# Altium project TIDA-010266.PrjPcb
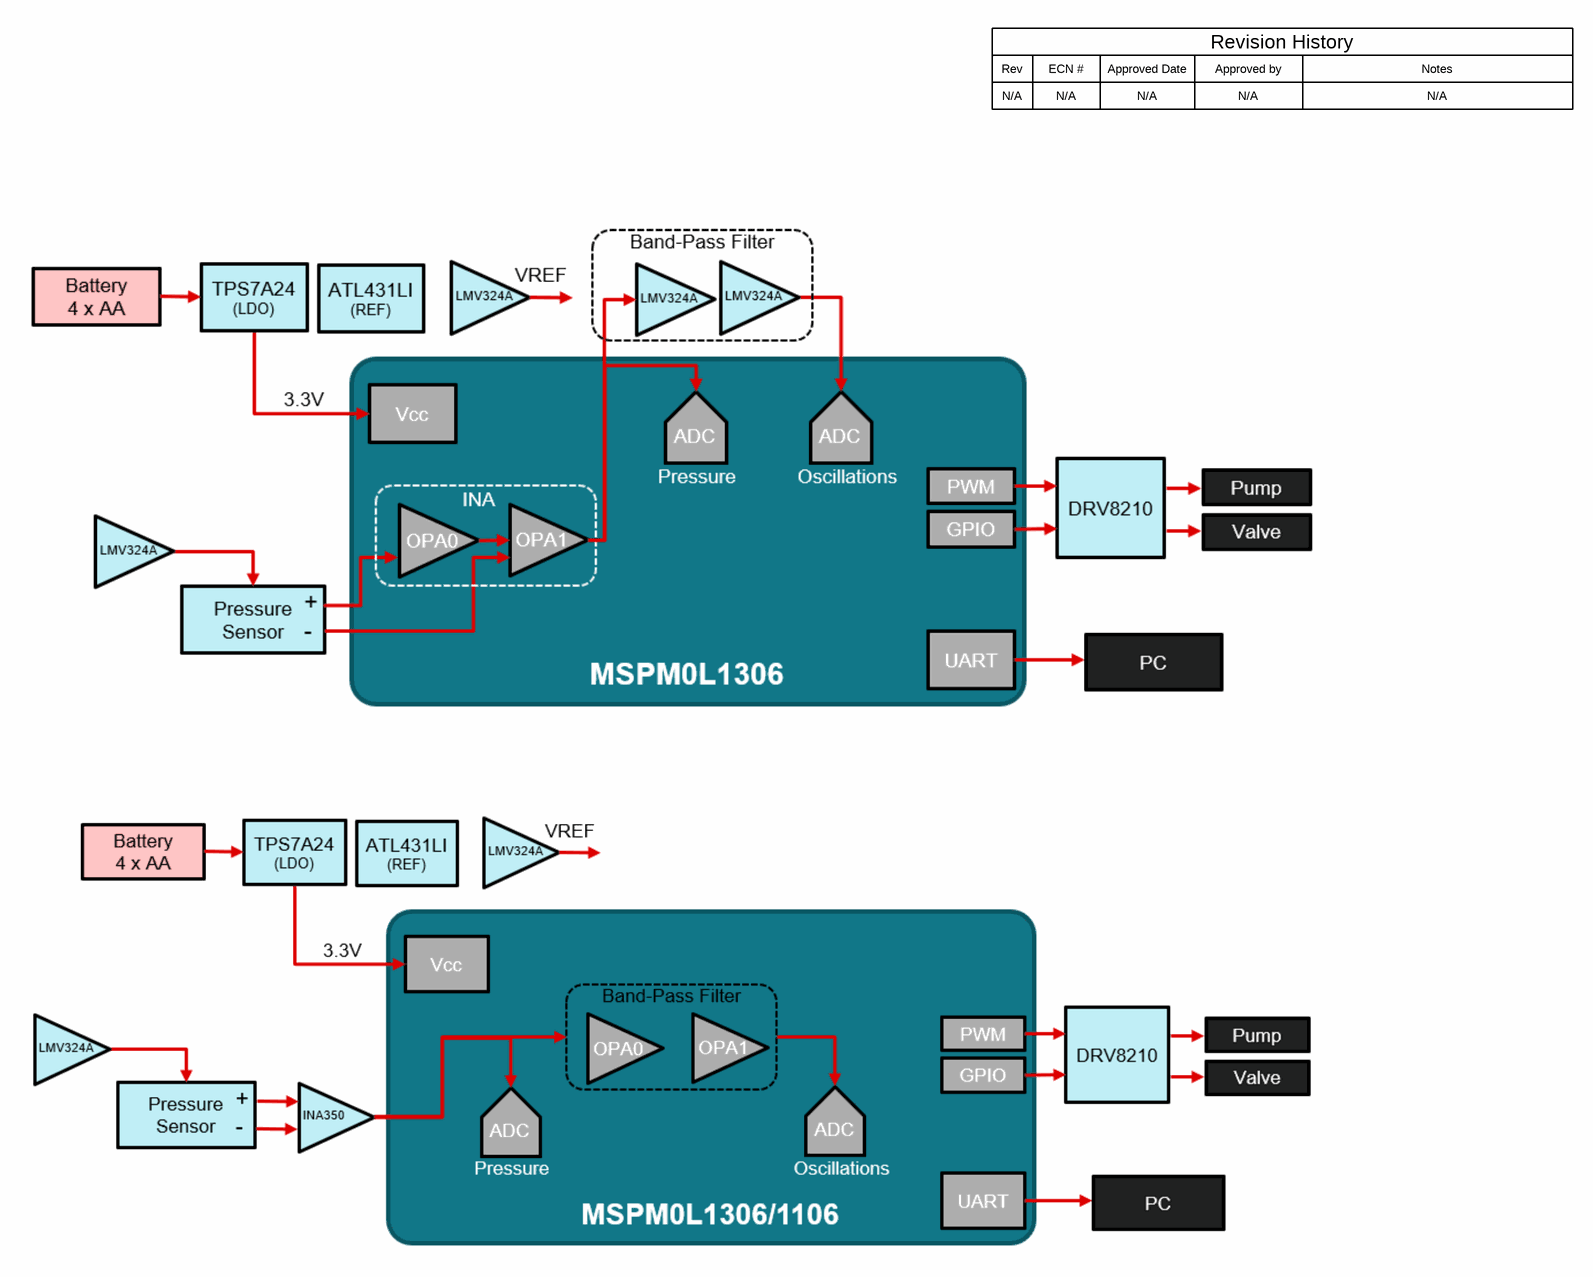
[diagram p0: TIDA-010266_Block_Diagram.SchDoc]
TID: 010266; TechSupport: http://www.ti.com/support; SCH_Rev: A; PRJ_Title: Low cost blood pressure and heart rate monitor; PRJ_Number: TIDA-010266; PRJ_Engineer: John Varela; PRJ_Customer: Public Release; PCB_Rev: A; PCB_Layout: John Varela; CopyrightYear: 2023
3 sheets, 89 parts. Net scope: global (net labels, ports and power ports of the same name join across sheets).
Board file: TIDA-010266.PcbDoc
Sheets:
  TIDA-010266_Block_Diagram.SchDoc
  TIDA-010266_BPM.SchDoc
  TIDA-010266_Hardware.SchDoc

## Sheet TIDA-010266_Block_Diagram.SchDoc
size 431 x 279 mm; Date: Not shown in title block; ApprovedBy: Not shown in title block; CheckedBy: Not shown in title block; Author: Not shown in title block; CompanyName: Not shown in title block; Engineer: Not shown in title block; Organization: Not shown in title block; Address1: Not shown in title block; Address2: Not shown in title block; Address3: Not shown in title block; Address4: Not shown in title block; DocumentNumber: 1; Revision: Use project parameter SCH_Rev; SheetNumber: 1; SheetTotal: 3; PageSetup: Record=PageOptions¦CenterHorizontal=True¦CenterVertical=True¦PrintScale=1.00¦XCorrection=1.00¦YCorrection=1.00¦PrintKind=0¦BorderSize=5000000¦LeftOffset=0¦BottomOffset=0¦Orientation=2¦PaperLength=1000¦PaperWidth=1000¦Scale=100¦PaperSource=15¦PrintQuality=600¦MediaType=1¦DitherType=10¦PaperKind=Letter¦PrintScaleMode=1

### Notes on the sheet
- Rev
- N/A
- ECN #
- Approved Date
- Approved by
- Revision History
- Notes

## Sheet TIDA-010266_BPM.SchDoc
size 431 x 279 mm; Date: Not shown in title block; ApprovedBy: Not shown in title block; CheckedBy: Not shown in title block; Author: Not shown in title block; CompanyName: Not shown in title block; Engineer: Not shown in title block; Organization: Not shown in title block; Address1: Not shown in title block; Address2: Not shown in title block; Address3: Not shown in title block; Address4: Not shown in title block; DocumentNumber: 2; Revision: Use project parameter SCH_Rev; SheetNumber: 2; SheetTotal: 3; PageSetup: Record=PageOptions¦CenterHorizontal=True¦CenterVertical=True¦PrintScale=1.00¦XCorrection=1.00¦YCorrection=1.00¦PrintKind=0¦BorderSize=5000000¦LeftOffset=0¦BottomOffset=0¦Orientation=2¦PaperLength=1000¦PaperWidth=1000¦Scale=100¦PaperSource=15¦PrintQuality=600¦MediaType=1¦DitherType=10¦PaperKind=Letter¦PrintScaleMode=1
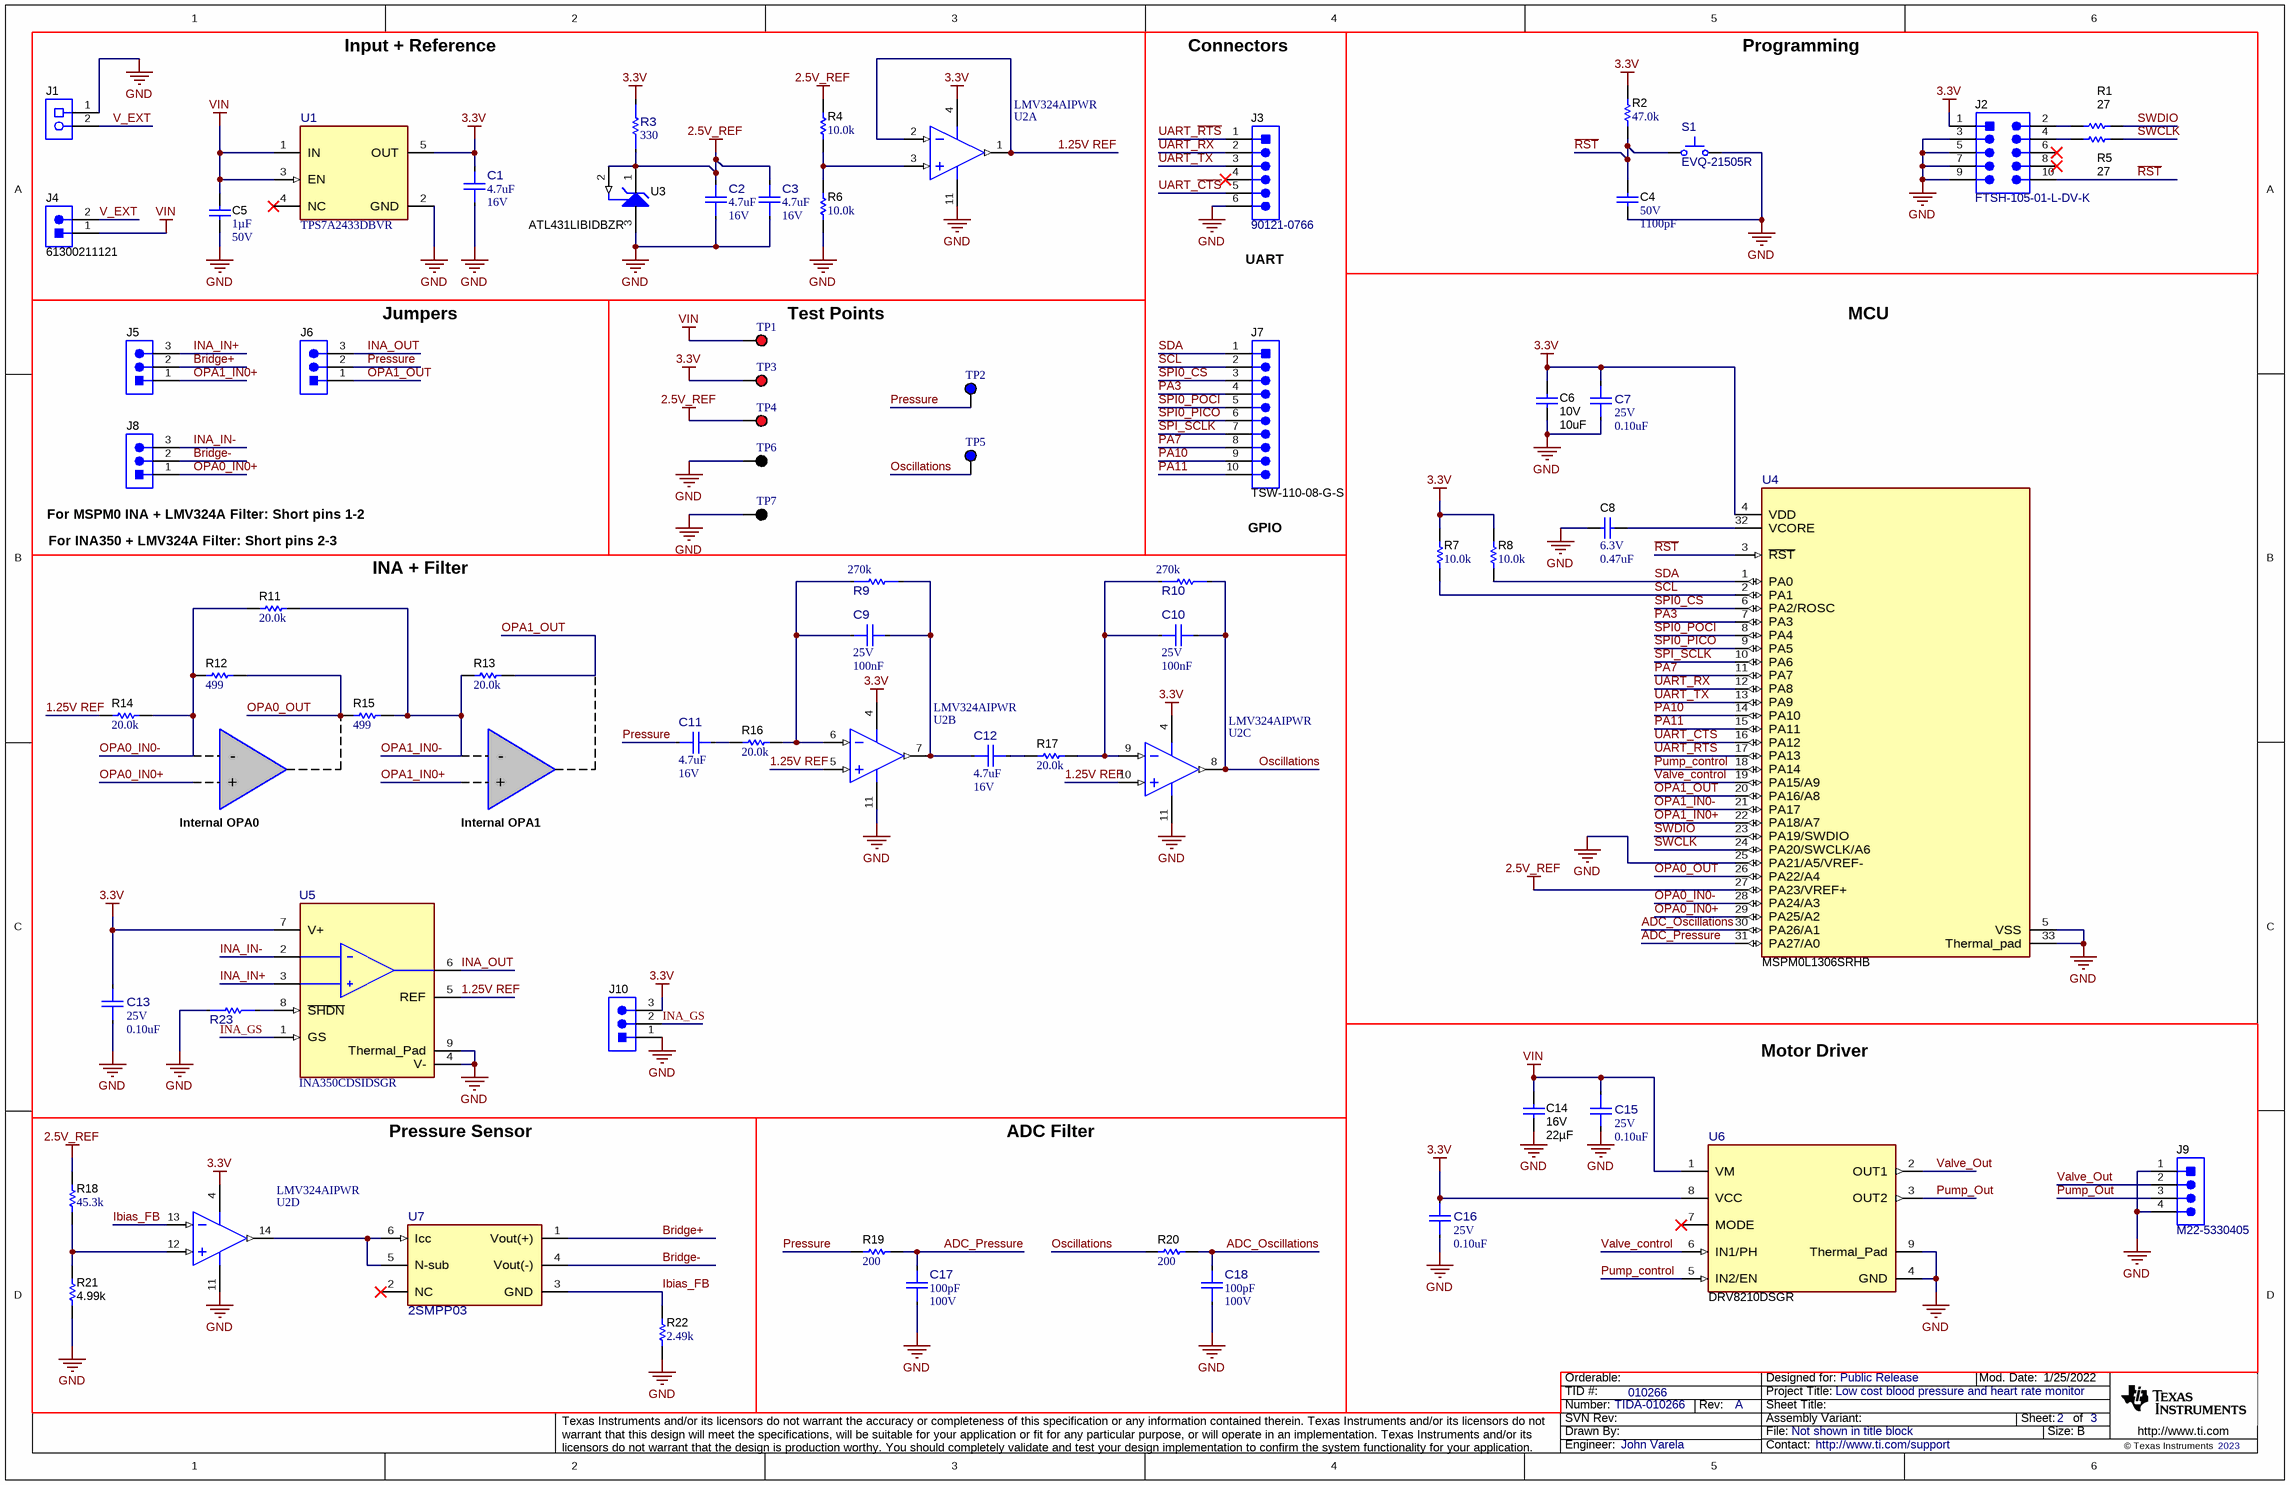
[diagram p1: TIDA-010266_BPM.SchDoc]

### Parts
C1  ValueDisplayed: 4.7uF  VDC_V: 16V  [FP-GRM188R61C475KE11D_0603-MFG]  (hidden comment: GRM188R61C475KE11D)
C2  ValueDisplayed: 4.7uF  VDC_V: 16V  [FP-GRM188R61C475KE11D_0603-MFG]  (hidden comment: GRM188R61C475KE11D)
C3  ValueDisplayed: 4.7uF  VDC_V: 16V  [FP-GRM188R61C475KE11D_0603-MFG]  (hidden comment: GRM188R61C475KE11D)
C4  VDC_V: 50V  ValueDisplayed: 1100pF  [0603]  (hidden comment: GRM1885C1H112JA01D)
C5  Cap_F: 1µF  VDC_V: 50V  [0805_HV]  (hidden comment: GCM21BR71H105KA03K)
C6  VDC_V: 10V  ValueDisplayed: 10uF  [0603]  (hidden comment: GRM188R61A106ME69D)
C7  ValueDisplayed: 0.10uF  VDC_V: 25V  [FP-GRM155R71E104KE14J_0402-MFG]  (hidden comment: GRM155R71E104KE14J)
C8  VDC_V: 6.3V  ValueDisplayed: 0.47uF  [0402]  (hidden comment: GRM155C80J474KE19D)
C9  VDC_V: 25V  Cap_F: 100nF  [FP-GCJ188R71E104KA12D_0603-MFG]  (hidden comment: GCJ188R71E104KA12D)
C10  VDC_V: 25V  Cap_F: 100nF  [FP-GCJ188R71E104KA12D_0603-MFG]  (hidden comment: GCJ188R71E104KA12D)
C11  ValueDisplayed: 4.7uF  VDC_V: 16V  [FP-GRM188R61C475KE11D_0603-MFG]  (hidden comment: GRM188R61C475KE11D)
C12  ValueDisplayed: 4.7uF  VDC_V: 16V  [FP-GRM188R61C475KE11D_0603-MFG]  (hidden comment: GRM188R61C475KE11D)
C13  ValueDisplayed: 0.10uF  VDC_V: 25V  [FP-GRM155R71E104KE14J_0402-MFG]  (hidden comment: GRM155R71E104KE14J)
C14  VDC_V: 16V  ValueDisplayed: 22µF  [0603]  (hidden comment: CL10A226MO7JZNC)
C15  ValueDisplayed: 0.10uF  VDC_V: 25V  [FP-GRM155R71E104KE14J_0402-MFG]  (hidden comment: GRM155R71E104KE14J)
C16  ValueDisplayed: 0.10uF  VDC_V: 25V  [FP-GRM155R71E104KE14J_0402-MFG]  (hidden comment: GRM155R71E104KE14J)
C17  ValueDisplayed: 100pF  VDC_V: 100V  [FP-GCM1885C2A101JA16J_0603-MFG]  (hidden comment: GCM1885C2A101JA16J)
C18  ValueDisplayed: 100pF  VDC_V: 100V  [FP-GCM1885C2A101JA16J_0603-MFG]  (hidden comment: GCM1885C2A101JA16J)
J1  CMP-0054828-1  [Wurth_691101710002]  (value not drawn)
J2  FTSH-105-01-L-DV-K  [Samtec_FTSH-105-01-x-DV-K]
J3  90121-0766  [Molex_90121-0766]
J4  61300211121  [WURTH_61300211121]
J5  61300311121  [WURTH_61300311121]  (value not drawn)
J6  61300311121  [WURTH_61300311121]  (value not drawn)
J7  TSW-110-08-G-S  [Samtec_TSW-110-08-x-S]
J8  61300311121  [WURTH_61300311121]  (value not drawn)
J9  M22-5330405  [Harwin_M22-5330405]
J10  61300311121  [WURTH_61300311121]  (value not drawn)
R1  ValueDisplayed: 27  [0603]  (hidden comment: CRCW060327R0JNEA)
R2  ValueDisplayed: 47.0k  [0603]  (hidden comment: CRCW060347K0FKEA)
R3  value 330  [FP-CRCW0603330RFKEA_0603-MFG]  (hidden comment: CRCW0603330RFKEA)
R4  ValueDisplayed: 10.0k  [0603]  (hidden comment: CRCW060310K0FKEA)
R5  ValueDisplayed: 27  [0603]  (hidden comment: CRCW060327R0JNEA)
R6  ValueDisplayed: 10.0k  [0603]  (hidden comment: CRCW060310K0FKEA)
R7  ValueDisplayed: 10.0k  [0603]  (hidden comment: CRCW060310K0FKEA)
R8  ValueDisplayed: 10.0k  [0603]  (hidden comment: CRCW060310K0FKEA)
R9  value 270k  [FP-CRCW0603270KFKEA_0603-MFG]  (hidden comment: CRCW0603270KFKEA)
R10  value 270k  [FP-CRCW0603270KFKEA_0603-MFG]  (hidden comment: CRCW0603270KFKEA)
R11  ValueDisplayed: 20.0k  [0603]  (hidden comment: CRCW060320K0FKEA)
R12  ValueDisplayed: 499  [0603]  (hidden comment: CRCW0603499RFKEAC)
R13  ValueDisplayed: 20.0k  [0603]  (hidden comment: CRCW060320K0FKEA)
R14  ValueDisplayed: 20.0k  [0603]  (hidden comment: CRCW060320K0FKEA)
R15  ValueDisplayed: 499  [0603]  (hidden comment: CRCW0603499RFKEAC)
R16  ValueDisplayed: 20.0k  [0603]  (hidden comment: CRCW060320K0FKEA)
R17  ValueDisplayed: 20.0k  [0603]  (hidden comment: CRCW060320K0FKEA)
R18  ValueDisplayed: 45.3k  [0603]  (hidden comment: CRCW060345K3FKEA)
R19  ValueDisplayed: 200  [0603]  (hidden comment: CRCW0603200RFKEA)
R20  ValueDisplayed: 200  [0603]  (hidden comment: CRCW0603200RFKEA)
R21  ValueDisplayed: 4.99k  [0603]  (hidden comment: CRCW06034K99FKEAC)
R22  ValueDisplayed: 2.49k  [0603]  (hidden comment: RT0603BRD072K49L)
R23  RC0402FR-070RL  [FP-RC0402FR-070RL_0402-MFG]  (value not drawn)
S1  EVQ-21505R  [SW_EVQ-21x05]
TP1  5000  [Keystone5000]  (value not drawn)
TP2  5117  [Keystone5117]  (value not drawn)
TP3  5000  [Keystone5000]  (value not drawn)
TP4  5000  [Keystone5000]  (value not drawn)
TP5  5117  [Keystone5117]  (value not drawn)
TP6  5001  [Keystone5001]  (value not drawn)
TP7  5001  [Keystone5001]  (value not drawn)
U1  TPS7A2433DBVR  [DBV0005A-MFG]
U2  LMV324AIPWR  [PW0014A-MFG]  (parts A,B,C,D of 4)
U3  ATL431LIBIDBZR  [DBZ0003A_N]
U4  MSPM0L1306SRHB  [RHB0032N-MFG]
U5  INA350CDSIDSGR  [DSG0008A-MFG]
U6  DRV8210DSGR  [DSG0008A-MFG]
U7  2SMPP03  [FP-2SMPP03_SMD6-MFG]

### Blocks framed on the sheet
Input + Reference: C1-C3 C5 J1 J4 R3 R4 R6 U1-U3
Connectors: J3 J7
Programming: C4 J2 R1 R2 R5 S1
INA + Filter: C9-C13 J10 R9-R17 R23 U2 U5
Motor Driver: C14-C16 J9 U6
Pressure Sensor: R18 R21 R22 U2 U7
ADC Filter: C17 C18 R19 R20

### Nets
2.5V_REF: C2.2 C3.2 R3.1 R4.2 R18.2 TP4.1 U3.1(CATHODE) U3.2(REF) U4.27(PA23/VREF+)
3.3V: C1.2 C6.1 C7.2 C13.2 C16.2 J2.1 J10.3 R2.2 R3.2 R7.2 R8.2 TP3.1 U1.5(OUT) U2.4(V+) U4.4(VDD) U5.7(V+) U6.8(VCC)
GND: C1.1 C2.1 C3.1 C4.2 C5.2 C6.2 C7.1 C8.2 C13.1 C14.2 C15.2 C16.1 C17.1 C18.1 J1.1 J2.3 J2.5 J2.7 J2.9 J3.6 J9.1 J9.4 J10.1 R6.1 R21.1 R22.1 R23.1 S1.2 TP6.1 TP7.1 U1.2(GND) U2.11(V-) U3.3(ANODE) U4.5(VSS) U4.25(PA21/A5/VREF-) U4.33(Thermal_pad) U5.4(V-) U5.9(Thermal_Pad) U6.4(GND) U6.9(Thermal_Pad)
VIN: C5.1 C14.1 C15.1 J4.1 TP1.1 U1.1(IN) U1.3(EN) U6.1(VM)
1.25V REF: R14.1 U2.1(OUTA) U2.2(INA-) U2.5(INB+) U2.10(INC+) U5.5(REF)
~{RST}: C4.1 J2.10 R2.1 S1.1 U4.3(~{RST})
ADC_Oscillations: C18.2 R20.2 U4.30(PA26/A1)
ADC_Pressure: C17.2 R19.2 U4.31(PA27/A0)
Bridge+: J5.2 U7.1(Vout(+))
Bridge-: J8.2 U7.4(Vout(-))
Ibias_FB: R22.2 U2.13(IND-) U7.3(GND)
INA_GS: J10.2 U5.1(GS)
INA_IN+: J5.3 U5.3(IN+)
INA_IN-: J8.3 U5.2(IN-)
INA_OUT: J6.3 U5.6(OUT)
OPA0_IN0+: J8.1 U4.29(PA25/A2)
OPA0_IN0-: R11.1 R12.1 R14.2 U4.28(PA24/A3)
OPA0_OUT: R12.2 R15.1 U4.26(PA22/A4)
OPA1_IN0+: J5.1 U4.22(PA18/A7)
OPA1_IN0-: R11.2 R13.1 R15.2 U4.21(PA17)
OPA1_OUT: J6.1 R13.2 U4.20(PA16/A8)
Oscillations: C10.2 R10.2 R20.1 TP5.1 U2.8(OUTC)
PA3: J7.4 U4.7(PA3)
PA7: J7.8 U4.11(PA7)
PA10: J7.9 U4.14(PA10)
PA11: J7.10 U4.15(PA11)
Pressure: C11.1 J6.2 R19.1 TP2.1
Pump_control: U4.18(PA14) U6.5(IN2/EN)
Pump_Out: J9.3 U6.3(OUT2)
SCL: J7.2 R7.1 U4.2(PA1)
SDA: J7.1 R8.1 U4.1(PA0)
SPI0_CS: J7.3 U4.6(PA2/ROSC)
SPI0_PICO: J7.6 U4.9(PA5)
SPI0_POCI: J7.5 U4.8(PA4)
SPI_SCLK: J7.7 U4.10(PA6)
SWCLK: R5.2 U4.24(PA20/SWCLK/A6)
SWDIO: R1.2 U4.23(PA19/SWDIO)
UART_~{CTS}: J3.5 U4.16(PA12)
UART_~{RTS}: J3.1 U4.17(PA13)
UART_RX: J3.2 U4.12(PA8)
UART_TX: J3.3 U4.13(PA9)
V_EXT: J1.2 J4.2
Valve_control: U4.19(PA15/A9) U6.6(IN1/PH)
Valve_Out: J9.2 U6.2(OUT1)
NetC8_1: C8.1 U4.32(VCORE)
NetC9_1: C9.1 R9.1 R16.2 U2.6(INB-)
NetC9_2: C9.2 C12.1 R9.2 U2.7(OUTB)
NetC10_1: C10.1 R10.1 R17.2 U2.9(INC-)
NetC11_2: C11.2 R16.1
NetC12_2: C12.2 R17.1
NetJ2_2: J2.2 R1.1
NetJ2_4: J2.4 R5.1
NetR4_1: R4.1 R6.2 U2.3(INA+)
NetR18_1: R18.1 R21.2 U2.12(IND+)
NetR23_2: R23.2 U5.8(~{SHDN})
NetU2_14: U2.14(OUTD) U7.5(N-sub) U7.6(Icc)

Not connected (* = marked no-connect by the designer): J2 6* 8*; J3 4*; U1 4(NC)*; U6 7(MODE)*; U7 2(NC)*

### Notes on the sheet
- (near J3) UART
- Jumpers
- (near TP1) Test Points
- MCU
- For INA350 + LMV324A Filter: Short pins 2-3
- (near J8) For MSPM0 INA + LMV324A Filter: Short pins 1-2
- GPIO
- -
- Internal OPA0
- +
- Internal OPA1

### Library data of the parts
C1-C3 C11 C12 = CMP-0098153-1: Chip Multilayer Ceramic Capacitors for General Purpose, 0603, 4.7uF, X5R, 15%, 10%, 16V; Manufacturer: Murata; SizeZ_mm: 0.95mm; Cap_F: 4.7µF; Value: 4.7µF; AEC Qualified: No
C4 = CMP-0007177-4: CAP, CERM, 1100 pF, 50 V, +/- 5%, C0G/NP0, 0603; Manufacturer: MuRata; TaMin_C: -55°C; Polarized: N; SizeAreaWB_mm2: 4.68; Value1: Unknown; U/M: EA; Value: 1100pF; TaMax_C: 125°C; SizeZ_mm: 1; SizeX_mm: 1.6; SizeY_mm: 0.8; SizeArea_mm2: 1.28; Cap_F: 1.1nF; AEC Category: Q200
C5 = CMP-0086249-1: CAP, CERM, 1 µF, 50 V,+/- 10%, X7R, AEC-Q200 Grade 1, 0805; Manufacturer: MuRata; Value: 1uF; AEC Qualified: Y; AEC Category: Q200; U/M: EA; AEC Grade: 1; SizeArea_mm2: 2.5; SizeAreaWB_mm2: 6.75; SizeZ_mm: 1.45; SizeX_mm: 2; Cap_Case: 0805; TaMax_C: 125°C; Polarized: N; SizeY_mm: 1.25; TaMin_C: -55°C
C6 = CMP-0007318-3: CAP, CERM, 10 uF, 10 V, +/- 20%, X5R, 0603; Manufacturer: MuRata; TaMin_C: -55°C; Polarized: N; SizeAreaWB_mm2: 4.68; Value1: Unknown; U/M: EA; Value: 10uF; TaMax_C: 85°C; SizeZ_mm: 1; SizeX_mm: 1.6; SizeY_mm: 0.8; SizeArea_mm2: 1.28; Cap_F: 10µF; AEC Category: Q200
C7 C13 C15 C16 = CMP-0095279-1: Chip Multilayer Ceramic Capacitors for General Purpose, 0402, 0.10uF, X7R, 15%, 10%, 25V; Manufacturer: Murata; Value: 100nF; SizeZ_mm: 0.55mm; AEC Qualified: No
C8 = CMP-0006525-2: CAP, CERM, 0.47 uF, 6.3 V, +/- 10%, X6S, 0402; Manufacturer: MuRata; TaMin_C: -55°C; Polarized: N; SizeAreaWB_mm2: 3; Value1: Unknown; U/M: EA; Value: 0.47uF; TaMax_C: 105°C; SizeZ_mm: 0.6; SizeX_mm: 1; SizeY_mm: 0.5; Cap_F: 470nF; AEC Category: Q200
C9 C10 = CMP-0095670-2: Cap Ceramic 0.1uF 25V X7R 10% Pad SMD 0603 Soft Termination +125°C Automotive T/R; Manufacturer: Murata; Value: 100nF; AEC Qualified: Yes; AEC Grade: Grade 1; SizeZ_mm: 0.9mm; TempCo: 15%
C14 = CMP-0081159-1: CAP, CERM, 22 µF, 16 V,+/- 20%, X5R, 0603; Manufacturer: Samsung; SizeAreaWB_mm2: 4.68; SizeArea_mm2: 1.28; AEC Qualified: N; AEC Category: Q200; Value: 22uF; TaMax_C: 85°C; SizeZ_mm: 1; TaMin_C: -55°C; SizeY_mm: 0.8; U/M: EA; SizeX_mm: 1.6
C17 C18 = CMP-0120248-1: Ceramic Capacitor for Automotive 100pF  ±5% 100VDC C0G 0603 Paper T/R; Manufacturer: Murata; AEC Grade: Grade 1; AEC Qualified: Yes; SizeZ_mm: 0.9mm; TempCo: 30ppm/°C
J1 = CMP-0054828-1: Terminal Block, 5 mm, 2x1, Tin, TH; PartNumber: 691 101 710 002; Manufacturer: Wurth Elektronik; CNHeader: FALSE; Green_Lifecycle: Active; Green_REACh: Passed; CT: TRUE
J2 = CMP-0075634-2: Header(Shrouded), 1.27mm, 5x2, Gold, SMT; Manufacturer: Samtec; Pitch_mm: 1.27; Gender: Male; Cert_CSA: Y; Current_A: 3.3A; Row_Count: 2
J3 = CMP-0055334-1: Header, 2.54mm, 6x1, Gold, R/A, TH; Manufacturer: Molex; CNHeader: TRUE; Current_A: 3A; Shrouded: N; Gender: Male; Voltage_V: 350V; Row_Count: 1; Pitch_mm: 2.54; CT: FALSE; Cert_UL: Y
J4 = CMP-0054794-2: Header, 2.54 mm, 2x1, Gold, TH; Manufacturer: Wurth Elektronik; Shrouded: N; Gender: Male; Green_REACh: Passed; Pitch_mm: 2.54; Green_Lifecycle: Active; Row_Count: 1; Cert_UL: Y
J5 J6 J8 J10 = CMP-0054796-1: Header, 2.54 mm, 3x1, Gold, TH; Manufacturer: Wurth Elektronik; Green_Lifecycle: Active; Green_REACh: Passed; CNHeader: TRUE; CT: FALSE
J7 = CMP-0055600-1: Header, 2.54mm, 10x1, Gold, TH; Manufacturer: Samtec; CNHeader: TRUE; Current_A: 6.3A; Shrouded: N; Gender: Male; Cert_CSA: Y; Voltage_V: 550V; Row_Count: 1; Pitch_mm: 2.54; CT: FALSE
J9 = CMP-0075150-1: Header, 2mm, 4x1, Gold, Black, R/A, SMT; Manufacturer: Harwin; CNHeader: True; Gender: Male; Row_Count: 1; Pitch_mm: 2; CT: False
R1 R5 = CMP-0025767-3: RES, 27, 5%, 0.1 W, 0603; Manufacturer: Vishay-Dale; Power_W: 100mW; TempCo: 200 ppm/C; Value_Code: 27R0; U/M: EA; Value: 27; EIA_Code: E24; SizeX_mm: 1.6; SizeY_mm: 0.8; SizeZ_mm: 1; Value2: 0.1W; SizeArea_mm2: 1.28; VDC_V: 75V; AEC Category: Q200
R2 = CMP-0022438-4: RES, 47.0 k, 1%, 0.1 W, AEC-Q200 Grade 0, 0603; Manufacturer: Vishay-Dale; Power_W: 100mW; TempCo: 100 ppm/C; Value_Code: 47k0; Value: 47.0k; Res_ohm: 47k; SizeX_mm: 1.6; SizeY_mm: 0.8; SizeZ_mm: 1; Value2: 0.1W; SizeArea_mm2: 1.28; AEC Qualified: Y; VDC_V: 75V; AEC Grade: 0; AEC Category: Q200
R3 = CMP-0120247-1: RES Thick Film, 330Ω, 1%, 0.1W, 100ppm/°C, 0603; Manufacturer: Vishay; Approved Alternate Part Number: 541-1.00HHCT-ND; AEC Grade: Grade 0; AEC Qualified: Yes; Power_W: 100mW; SizeZ_mm: 0.5mm; VDC_V: 75V
R4 R6-R8 = CMP-0021998-4: RES, 10.0 k, 1%, 0.1 W, AEC-Q200 Grade 0, 0603; Manufacturer: Vishay-Dale; Power_W: 100mW; TempCo: 100 ppm/C; Value_Code: 10k0; Value: 10.0k; EIA_Code: E96; Res_ohm: 10k; SizeX_mm: 1.6; SizeY_mm: 0.8; SizeZ_mm: 1; Value2: 0.1W; SizeArea_mm2: 1.28; AEC Qualified: Y; VDC_V: 75V; AEC Category: Q200; AEC Grade: 0
R9 R10 = CMP-0120246-1: RES Thick Film, 270kΩ, 1%, 0.1W, 100ppm/°C, 0603; Manufacturer: Vishay; Approved Alternate Part Number: 541-1.00HHCT-ND; AEC Grade: Grade 0; AEC Qualified: Yes; Power_W: 100mW; SizeZ_mm: 0.5mm; VDC_V: 75V
R11 R13 R14 R16 R17 = CMP-0022204-4: RES, 20.0 k, 1%, 0.1 W, AEC-Q200 Grade 0, 0603; Manufacturer: Vishay-Dale; Power_W: 100mW; TempCo: 100 ppm/C; Value_Code: 20k0; Value: 20.0k; EIA_Code: E96; Res_ohm: 20k; SizeX_mm: 1.6; SizeY_mm: 0.8; SizeZ_mm: 1; Value2: 0.1W; SizeArea_mm2: 1.28; AEC Qualified: Y; VDC_V: 75V; AEC Category: Q200; AEC Grade: 0
R12 R15 = CMP-0082532-1: RES, 499, 1%, 0.1 W, 0603; Manufacturer: Vishay-Dale; Power_W: 100mW; TempCo: 100 ppm/C; SizeAreaWB_mm2: 4.68; Value_Code: 499R; Value: 499; EIA_Code: E96; SizeX_mm: 1.6; SizeY_mm: 0.8; SizeZ_mm: 1; Value2: 0.1W; SizeArea_mm2: 1.28; AEC Qualified: N; VDC_V: 75V; AEC Category: Q200
R18 = CMP-0022430-4: RES, 45.3 k, 1%, 0.1 W, AEC-Q200 Grade 0, 0603; Manufacturer: Vishay-Dale; Power_W: 100mW; TempCo: 100 ppm/C; Value_Code: 45k3; Value: 45.3k; EIA_Code: E96; SizeX_mm: 1.6; SizeY_mm: 0.8; SizeZ_mm: 1; Value2: 0.1W; SizeArea_mm2: 1.28; AEC Qualified: Y; VDC_V: 75V; AEC Category: Q200; AEC Grade: 0
R19 R20 = CMP-0022201-5: RES, 200, 1%, 0.1 W, AEC-Q200 Grade 0, 0603; Manufacturer: Vishay-Dale; Power_W: 100mW; TempCo: 100 ppm/C; Value_Code: 200R; Value: 200; EIA_Code: E96; SizeX_mm: 1.6; SizeY_mm: 0.8; SizeZ_mm: 1; Value2: 0.1W; SizeArea_mm2: 1.28; AEC Qualified: Y; VDC_V: 75V; AEC Category: Q200; AEC Grade: 0
R21 = CMP-0082533-1: RES, 4.99 k, 1%, 0.1 W, 0603; Manufacturer: Vishay-Dale; Power_W: 100mW; TempCo: 100 ppm/C; SizeAreaWB_mm2: 4.68; Value_Code: 4k99; Value: 4.99k; EIA_Code: E96; SizeX_mm: 1.6; SizeY_mm: 0.8; SizeZ_mm: 1; Value2: 0.1W; SizeArea_mm2: 1.28; AEC Qualified: N; VDC_V: 75V; AEC Category: Q200
R22 = CMP-0024072-3: RES, 2.49 k, 0.1%, 0.1 W, 0603; Manufacturer: Yageo America; Power_W: 100mW; TempCo: 25 ppm/C; Value_Code: 2k49; U/M: EA; Value: 2.49k; EIA_Code: E192; SizeX_mm: 1.6; SizeY_mm: 0.8; SizeZ_mm: 1; Value2: 0.1W; SizeArea_mm2: 1.28; VDC_V: 75V; AEC Category: Q200
R23 = CMP-0095689-1: Jumper 0.063W, 1/16W Chip Resistor 0402 (1005 Metric) Moisture Resistant Thick Film; Manufacturer: Yageo; AEC Qualified: No; Value: 0; Power_W: 63mW; SizeZ_mm: 0.4mm
S1 = CMP-0002172-2: Switch, Tactile, SPST-NO, 0.02A, 15V, TH; Manufacturer: Panasonic; CurrentRating_mA: 20A; PositionCount: 1; SwitchFunction: Off-Mom
TP1 TP3 TP4 = CMP-0055137-1: Test Point, Miniature, Red, TH; Manufacturer: Keystone; CNHeader: FALSE; Green_Lifecycle: Active; Green_REACh: Passed; ContactFinish: Silver; CT: TRUE
TP2 TP5 = CMP-0055154-1: Test Point, Miniature, Blue, TH; Manufacturer: Keystone; CNHeader: FALSE; Green_Lifecycle: Active; Green_REACh: Passed; ContactFinish: Silver; CT: TRUE
TP6 TP7 = CMP-0055138-1: Test Point, Miniature, Black, TH; Manufacturer: Keystone; CNHeader: FALSE; Green_Lifecycle: Active; Green_REACh: Passed; ContactFinish: Silver; CT: TRUE
U1 = CMP-0120272-1: 200-mA, 18-V, ultra-low-IQ, low-dropout (LDO) voltage regulator with enable 5-SOT-23 -40 to 125; Manufacturer: Texas Instruments; SizeZ_mm: 1.45mm; AEC Qualified: No; Accuracy Percentage: 1.25%; Dropout Voltage: 160mV; Max Supply Voltage: 18V; Min Supply Voltage: 3.8V; Nominal Supply Current: 2-15uA; Number Of Outputs: 1; Output Type: Fixed; Output Voltage: 3.3V; Standoff Height: 0mm; TJmax_C: +125°C
U2 = CMP-0120268-2: Quad, 5.5-V, 1-MHz, 4-mV offset voltage, RRO operational amplifier 14-TSSOP -40 to 125; Manufacturer: Texas Instruments; SizeZ_mm: 1.2mm; AEC Qualified: No; Gain Bandwidth: 1MHz; Input Bias Current: 0.00001uA; Input Offset Voltage: 1mV; Max Dual Supply Voltage: 2.75V; Max Supply Voltage: 5.5V; Min Dual Supply Voltage: 1.25V; Min Supply Voltage: 2.5V; Nominal Supply Current: 70uA; Number Of Channels: 4; Output Current Per Channel: 40mA; Response Time: 4us; Standoff Height: 0.05mm; TaMax_C: +125°C; TaMin_C: -40°C; TJmax_C: +150°C; Voltage Gain: 98dB; AEC Category: Q200; CompType: IC
U3 = CMP-0084732-1: High Bandwidth Low-Iq Programmable Shunt Regulator, DBZ0003A (SOT-23-3); Manufacturer: Texas Instruments; SizeArea_mm2: 7.5; SizeY_mm: 3; SizeX_mm: 2.5; SizeAreaWB_mm2: 14; AEC Category: Q200; SizeZ_mm: 1.12; AEC Qualified: N; CompType: IC
U4 = CMP-0093968-1: MSPM0L130x Mixed-Signal Microcontrollers; Manufacturer: Texas Instruments; Number Of Pwm Channels: 8; TJmax_C: +130°C; Interface: I2C,SPI,UART,LIN,IrDA,SMBus; Number Of I2C Channels: 2; Memory Size: 64KBytes; Core Architecture: ARM Cortex-M0+; Number Of Spi Channels: 1; Min Supply Voltage: 1.62V; Ram Size: 4KBytes; Data Bus Width: 32bits; TaMax_C: +125°C; Frequency_Fixed: 32MHz; Memory Type: FLASH; Number Of Adc Channels: 10; Standoff Height: 0mm; AEC Qualified: No; Number Of I/Os: 28; TaMin_C: -40°C; SizeZ_mm: 1mm; Max Supply Voltage: 3.6V; Number Of Timers/Counters: 4
U5 = CMP-0120266-1: Cost and Size Optimized, Low Power, 1.8-V to 5.5-V Selectable Gain Instrumentation Amplifier; Manufacturer: Texas Instruments; SizeZ_mm: 0.8mm; AEC Qualified: No; Bandwidth: 100kHz; Input Bias Current: 0.00000065uA; Input Offset Voltage: 0.2mV; Max Dual Supply Voltage: 2.75V; Max Supply Voltage: 5.5V; Min Dual Supply Voltage: 900mV; Min Supply Voltage: 1.8V; Nominal Supply Current: 100uA; Number Of Channels: 1; Output Current Per Channel: 20mA; Response Time: 85us; Standoff Height: 0mm; TJmax_C: +150°C; Voltage Gain: 0.001V/mV
U6 = CMP-0090268-2: 11V, 1A H-bridge motor driver, PWM, PH/EN, ½ bridge control, with low power sleep mode; Manufacturer: Texas Instruments; Motor Type: Brushed; AEC Category: Q200; SizeZ_mm: 0.8mm; AEC Qualified: No; Min Supply Voltage: 1.65V; TJmax_C: +150°C; Switching Frequency: 100kHz; TaMax_C: +125°C; Number Of Outputs: 2; Standoff Height: 0mm; TaMin_C: -40°C; CompType: IC
U7 = CMP-0120245-1: Pressure Sensor ±7.25PSI (±50kPa) Compound Male - 0.1" (2.59mm) Tube -43 mV ~ 42 mV 6-SMD Module; Manufacturer: Omron Electronics Inc-EMC Div; AEC Qualified: No; Operating Supply Current: 100uA; Port Style: Barbless; Sensor Output: Analog Voltage; TaMax_C: +100°C; TaMin_C: -10°C

## Sheet TIDA-010266_Hardware.SchDoc
size 431 x 279 mm; Date: Not shown in title block; ApprovedBy: Not shown in title block; CheckedBy: Not shown in title block; Author: Not shown in title block; CompanyName: Not shown in title block; Engineer: Not shown in title block; Organization: Not shown in title block; Address1: Not shown in title block; Address2: Not shown in title block; Address3: Not shown in title block; Address4: Not shown in title block; DocumentNumber: 3; Revision: Use project parameter SCH_Rev; SheetNumber: 3; SheetTotal: 3; PageSetup: Record=PageOptions¦CenterHorizontal=True¦CenterVertical=True¦PrintScale=1.00¦XCorrection=1.00¦YCorrection=1.00¦PrintKind=0¦BorderSize=5000000¦LeftOffset=0¦BottomOffset=0¦Orientation=2¦PaperLength=1000¦PaperWidth=1000¦Scale=100¦PaperSource=15¦PrintQuality=600¦MediaType=1¦DitherType=10¦PaperKind=Letter¦PrintScaleMode=1
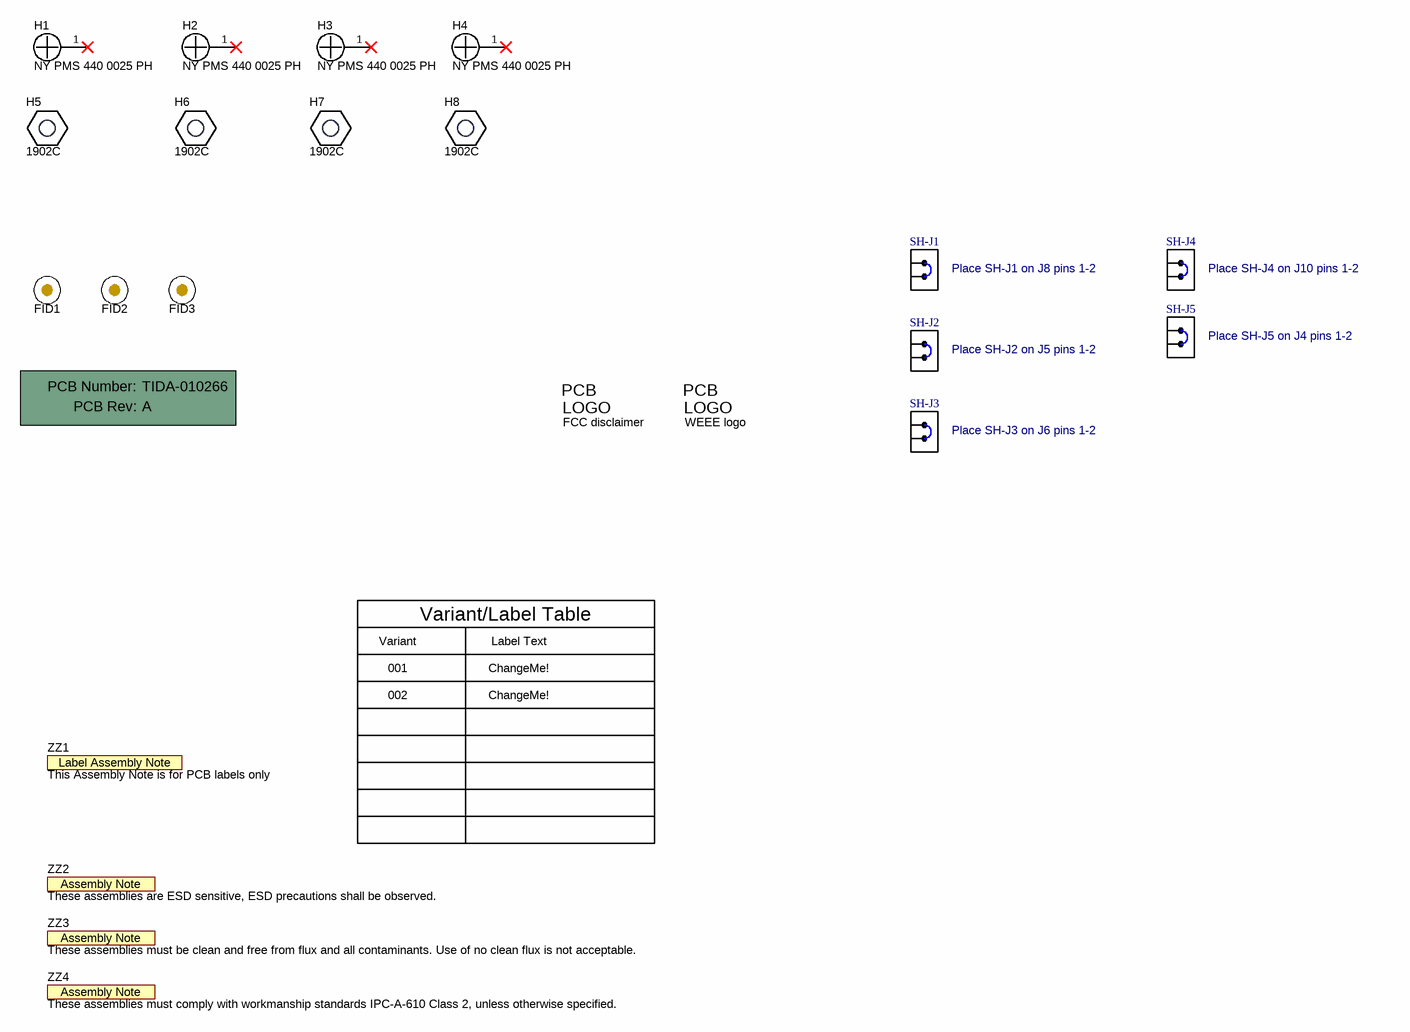
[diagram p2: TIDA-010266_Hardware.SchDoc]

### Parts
!PCB1  Printed Circuit Board  (value not drawn)  (mechanical)
FID1  Fiducial  [Fiducial10-20]  (value not drawn)
FID2  Fiducial  [Fiducial10-20]  (value not drawn)
FID3  Fiducial  [Fiducial10-20]  (value not drawn)
H1  NY PMS 440 0025 PH  [NY PMS 440 0025 PH]
H2  NY PMS 440 0025 PH  [NY PMS 440 0025 PH]
H3  NY PMS 440 0025 PH  [NY PMS 440 0025 PH]
H4  NY PMS 440 0025 PH  [NY PMS 440 0025 PH]
H5  1902C  [Keystone_1902C]
H6  1902C  [Keystone_1902C]
H7  1902C  [Keystone_1902C]
H8  1902C  [Keystone_1902C]
Logo3  FCC disclaimer  [FCC_disclaimer]  (no BOM)
Logo4  WEEE logo  [WEEE_Minimum]  (no BOM)
SH-J1  Place SH-J1 on J8 pins 1-2  [SNT-100-BK-G]
SH-J2  Place SH-J2 on J5 pins 1-2  [SNT-100-BK-G]
SH-J3  Place SH-J3 on J6 pins 1-2  [SNT-100-BK-G]
SH-J4  Place SH-J4 on J10 pins 1-2  [SNT-100-BK-G]
SH-J5  Place SH-J5 on J4 pins 1-2  [SNT-100-BK-G]
ZZ1  This Assembly Note is for PCB labels only  [AssemblyNoteLabel]  (no BOM)
ZZ2  These assemblies are ESD sensitive, ESD precautions shall be observed.  [AssemblyNote]  (no BOM)
ZZ3  These assemblies must be clean and free from flux and all contaminants. Use of no clean flux is not acceptable.  [AssemblyNote]  (no BOM)
ZZ4  These assemblies must comply with workmanship standards IPC-A-610 Class 2, unless otherwise specified.  [AssemblyNote]  (no BOM)

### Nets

Not connected (* = marked no-connect by the designer): H1 1*; H2 1*; H3 1*; H4 1*

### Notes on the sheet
- Variant
- Variant/Label Table
- Label Text
- 001
- 002
- ChangeMe!

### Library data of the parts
!PCB1 = CMP-0003618-2: Manufacturer: Any; PartNumber: TIDA-010266
FID1-FID3 = CMP-0077181-1: Fiducial mark.  There is nothing to buy or mount.
H1-H4 = CMP-0003617-1: Machine Screw, Round, #4-40 x 1/4, Nylon, Philips panhead; Manufacturer: B&F Fastener Supply; CompType: Hardware
H5-H8 = CMP-0003610-1: Standoff, Hex, 0.5"L #4-40 Nylon; Manufacturer: Keystone; CompType: Hardware
Logo3 = CMP-0074847-1: FCC_disclaimer; Library Reference: Logo
Logo4 = CMP-0074769-1
SH-J1-SH-J5 = CMP-0003623-3: Shunt, 100mil, Gold plated, Black; Alternate PartNumber: 969102-0000-DA; Manufacturer: Samtec; Alternate Manufacturer: 3M; Value: 1x2
ZZ1 = CMP-0003616-3
ZZ2 = CMP-0077236-1
ZZ3 = CMP-0077237-1
ZZ4 = CMP-0077238-1

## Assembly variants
001: not fitted FID1 FID2 FID3 R23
